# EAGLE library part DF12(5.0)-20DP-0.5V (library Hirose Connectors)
Connector, Header, board-board, 20-pin. Dual Row, 5mm stack height, 0.5mm Pitch (Hirose)
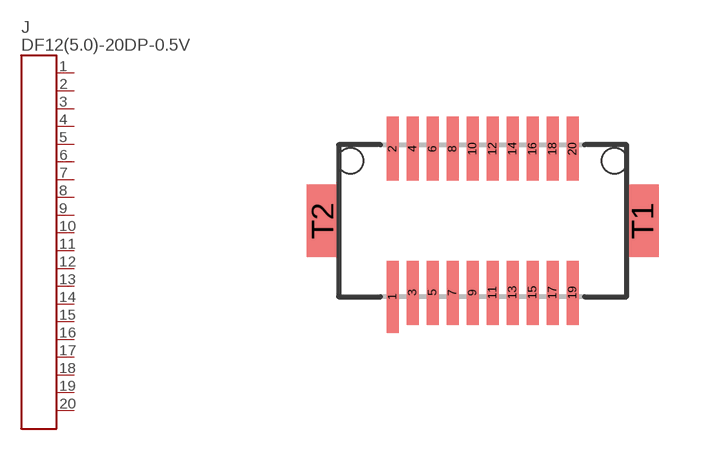
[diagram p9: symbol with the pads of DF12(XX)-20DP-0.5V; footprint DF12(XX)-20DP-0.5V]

Designator prefix J

## DF12(5.0)-20DP-0.5V  [DF12(XX)-20DP-0.5V]
1  P$1
2  P$2
3  P$3
4  P$4
5  P$5
6  P$6
7  P$7
8  P$8
9  P$9
10  P$10
11  P$11
12  P$12
13  P$13
14  P$14
15  P$15
16  P$16
17  P$17
18  P$18
19  P$19
20  P$20

## Footprint DF12(XX)-20DP-0.5V (pad centres in mm)
smd 0.3 x 1.8: 1 -2.25,-1.9
smd 0.3 x 1.6: 2 -2.25,1.8; 3 -1.75,-1.8; 4 -1.75,1.8; 5 -1.25,-1.8; 6 -1.25,1.8; 7 -0.75,-1.8; 8 -0.75,1.8; 9 -0.25,-1.8; 10 -0.25,1.8; 11 0.25,-1.8; 12 0.25,1.8; 13 0.75,-1.8; 14 0.75,1.8; 15 1.25,-1.8; 16 1.25,1.8; 17 1.75,-1.8; 18 1.75,1.8; 19 2.25,-1.8; 20 2.25,1.8
smd 0.8 x 1.8: T1 4,0; T2 -4,0
hole 0.635 at 3.3,1.5
hole 0.635 at -3.3,1.5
